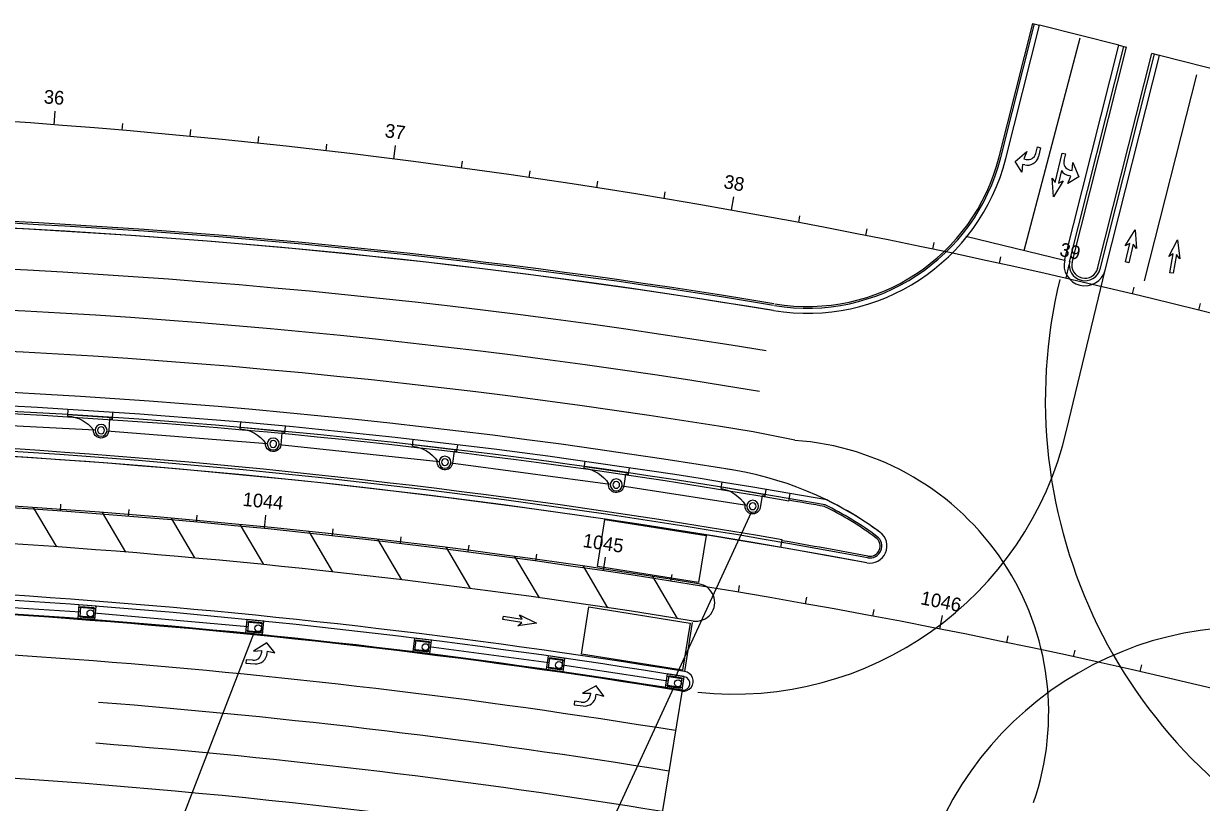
# Model space of a CAD drawing. Extents: x 468143 to 491361, y 1438528 to 1468730.
# Drawn here: x 486680.1 to 487025, y 1467383.7 to 1467611.7 of the extents above; entities that cross this region are included whole.
import ezdxf

# ---------------------------------------------------------------- set-up
doc = ezdxf.new("R2010")
doc.units = 0
doc.layers.add('Default', color=7, linetype='Continuous')
doc.layers.add('Xreference_dp', color=7, linetype='Continuous')

# ---------------------------------------------------------------- blocks, each defined once
blk = doc.blocks.new('POINT_DISPLAY')
at = {"layer": 'Default'}
blk.add_line((0, 0), (0, 0), dxfattribs=at)
blk = doc.blocks.new('InltCurb7_40')
at = {"layer": 'Default'}
for p, q in [((2.5, 4), (-2.5, 4)), ((-2.5, 4), (-2.5, 0)), ((2.5, 0), (2.5, 4)), ((2.5, 3.25), (-2.5, 3.25)), ((-2.5, 0.75), (2.5, 0.75)), ((-2.5, 0), (2.5, 0))]:
    blk.add_line(p, q, dxfattribs=at)
blk.add_lwpolyline([(-2, 0.5), (2, 0.5), (2, 3.5), (-2, 3.5)], close=True, dxfattribs=at)
blk.add_circle((-1.04, 2.19), 1, dxfattribs=at)
for p in [(-2, 3.5), (0, 4), (0, 3.5), (0, 3.5), (2, 3.5), (-2, 2), (-2, 2), (-2, 0.5), (0, 2), (0, 2), (0, 0.5), (0, 0.5), (0, 0), (0, 0), (2, 2), (2, 2), (2, 0.5)]:
    blk.add_blockref('POINT_DISPLAY', p, dxfattribs=at)
blk = doc.blocks.new('InltCurb1_35')
at = {"layer": 'Default'}
for p, q in [((2.25, 2), (2.25, 5.5)), ((-10, 2), (-10, 0)), ((-10, 1.5), (3, 1.5)), ((3, 2), (2.25, 2)), ((3, 0), (3, 2))]:
    blk.add_line(p, q, dxfattribs=at)
for radius in [1.75, 1]:
    blk.add_circle((0, 5.5), radius, dxfattribs=at)
for centre, radius, start, end in [((0, 5.5), 2.25, 0, 180), ((-9.85, 12), 10, 269.1432, 319.4677)]:
    blk.add_arc(centre, radius, start, end, dxfattribs=at)
for p in [(-0.66, 7.12), (0, 7.75), (0, 7.25), (0, 7.25), (0.7, 7.1), (-1.75, 5.5), (-1.75, 5.5), (-1.62, 4.84), (-1.6, 6.2), (-1.26, 4.28), (-1.22, 6.76), (-0.7, 3.9), (0, 5.5), (0, 5.5), (0, 3.75), (0, 3.75), (0.66, 3.88), (1.22, 4.24), (1.26, 6.72), (1.6, 4.8), (1.62, 6.16), (1.75, 5.5), (1.75, 5.5), (0, 0), (0, 0)]:
    blk.add_blockref('POINT_DISPLAY', p, dxfattribs=at)
blk = doc.blocks.new('DALeftTurn_1')
at = {"layer": 'Default'}
for points in [[(5.67, 3.17), (2, 0.5), (4.33, 0.83), (4.33, 0.17)], [(6, 0.17), (6, 0.83), (8.25, 0.5), (5.67, 3.17)], [(2, -2.17), (0, -2.17), (0, -3.17), (2.67, -3.17)]]:
    blk.add_lwpolyline(points, dxfattribs=at)
for centre, radius in [((2, 0.17), 2.33), ((2.67, 0.17), 3.33)]:
    blk.add_arc(centre, radius, 270, 0, dxfattribs=at)
blk = doc.blocks.new('DAThru_1')
at = {"layer": 'Default'}
blk.add_lwpolyline([(4.58, -1.67), (5.58, -0.5), (0, -0.5), (0, 0.5), (5.58, 0.5), (4.58, 1.67), (9.83, 0), (4.58, -1.67)], dxfattribs=at)
blk = doc.blocks.new('DALeftThru')
at = {"layer": 'Default'}
for points in [[(4.33, 0.83), (2, 0.5), (5.67, 3.17), (8.25, 0.5), (6, 0.83), (6, 0.17)], [(4.33, 0.17), (4.33, 0.83)], [(5.05, -2.17), (8.83, -2.17), (7.83, -1), (13.08, -2.67), (7.83, -4.33), (8.83, -3.17), (0, -3.17), (0, -2.17), (2, -2.17)]]:
    blk.add_lwpolyline(points, dxfattribs=at)
for centre, radius, start, end in [((2, 0.17), 2.33, 270, 0), ((2.67, 0.17), 3.33, 315.573, 360)]:
    blk.add_arc(centre, radius, start, end, dxfattribs=at)
blk = doc.blocks.new('DARightTurn')
at = {"layer": 'Default'}
for points in [[(2, 2.17), (0, 2.17), (0, 3.17), (2.67, 3.17)], [(5.67, -3.17), (2, -0.5), (4.33, -0.83), (4.33, -0.17)], [(6, -0.17), (6, -0.83), (8.25, -0.5), (5.67, -3.17)]]:
    blk.add_lwpolyline(points, dxfattribs=at)
for centre, radius in [((2, -0.17), 2.33), ((2.67, -0.17), 3.33)]:
    blk.add_arc(centre, radius, 360, 90, dxfattribs=at)
blk = doc.blocks.new('DAMerge_2')
at = {"layer": 'Default'}
blk.add_lwpolyline([(0.71, -4.09), (0, -3.39), (3.95, 0.56), (2.42, 0.68), (7.31, 3.21), (4.77, -1.68), (4.66, -0.15), (0.71, -4.09)], dxfattribs=at)
blk = doc.blocks.new('DAMerge_6')
at = {"layer": 'Default'}
blk.add_lwpolyline([(0.71, -4.09), (0, -3.39), (3.95, 0.56), (2.42, 0.68), (7.31, 3.21), (4.77, -1.68), (4.66, -0.15), (0.71, -4.09)], dxfattribs=at)

msp = doc.modelspace()

# ---------------------------------------------------------------- linework, layer by layer
at = {"layer": 'Xreference_dp'}
for p, q in [((486965.81, 1467572.63), (486975.67, 1467611.67)), ((486966.29, 1467572.5), (486976.16, 1467611.55)), ((486967.74, 1467572.14), (486977.61, 1467611.18)), ((486967.74, 1467572.14), (486977.61, 1467611.18)), ((486975.67, 1467611.67), (486977.61, 1467611.18)), ((487000.88, 1467605.3), (486977.61, 1467611.18)), ((486973.09, 1467545.2), (486989.53, 1467607.45)), ((486984.97, 1467542.32), (487000.88, 1467605.3)), ((486984.97, 1467542.32), (487000.88, 1467605.3)), ((486986.42, 1467541.95), (487002.33, 1467604.93)), ((486987.15, 1467541.77), (487003.06, 1467604.75)), ((487000.88, 1467605.3), (487003.06, 1467604.75)), ((486994.64, 1467540), (487010.53, 1467602.86)), ((486995.37, 1467539.82), (487011.25, 1467602.68)), ((486996.82, 1467539.45), (487012.71, 1467602.31)), ((486996.82, 1467539.45), (487012.71, 1467602.31)), ((487012.71, 1467602.31), (487010.53, 1467602.86)), ((487035.98, 1467596.43), (487012.71, 1467602.31)), ((487008.41, 1467536.34), (487023.66, 1467596.69)), ((486689.08, 1467582.05), (486689.38, 1467586.04)), ((486709.02, 1467580.44), (486709.19, 1467582.43)), ((486728.93, 1467578.63), (486729.13, 1467580.62)), ((486748.83, 1467576.62), (486749.04, 1467578.61)), ((486768.71, 1467574.41), (486768.94, 1467576.4)), ((486788.57, 1467572.01), (486789.07, 1467575.98)), ((486808.4, 1467569.4), (486808.67, 1467571.39)), ((486828.2, 1467566.6), (486828.49, 1467568.58)), ((486847.97, 1467563.6), (486848.28, 1467565.58)), ((486867.71, 1467560.4), (486868.04, 1467562.38)), ((486887.42, 1467557.01), (486888.12, 1467560.95)), ((486907.1, 1467553.42), (486907.47, 1467555.39)), ((486926.74, 1467549.63), (486927.13, 1467551.6)), ((486984.9, 1467542.34), (486956.09, 1467549.31)), ((486946.34, 1467545.65), (486946.74, 1467547.61)), ((486965.9, 1467541.47), (486966.32, 1467543.43)), ((486985.41, 1467537.1), (486986.31, 1467541)), ((486985.52, 1467492.5), (486996.82, 1467539.45)), ((487004.88, 1467532.53), (487005.35, 1467534.48)), ((487024.31, 1467527.77), (487024.79, 1467529.71)), ((486654.08, 1467495.19), (486701.06, 1467492.71)), ((486704.55, 1467492.47), (486751.48, 1467488.76)), ((486905.94, 1467489.67), (486893.74, 1467492.15)), ((486754.96, 1467488.43), (486801.79, 1467483.48)), ((486805.26, 1467483.07), (486851.94, 1467476.88)), ((486855.41, 1467476.38), (486891.91, 1467470.67)), ((486904.19, 1467471.87), (486904.58, 1467474.09)), ((486689.84, 1467458.5), (486683.04, 1467469.99)), ((486690.92, 1467468.95), (486691.06, 1467470.94)), ((486710.08, 1467456.95), (486703.23, 1467468.53)), ((486710.86, 1467467.43), (486711.03, 1467469.42)), ((486730.31, 1467455.22), (486723.41, 1467466.87)), ((486730.79, 1467465.72), (486730.97, 1467467.71)), ((486750.7, 1467463.82), (486751.1, 1467467.8)), ((486871.02, 1467420.38), (486893.33, 1467468.65)), ((486750.52, 1467453.28), (486743.57, 1467465.02)), ((486770.71, 1467451.15), (486763.71, 1467462.97)), ((486770.59, 1467461.73), (486770.81, 1467463.71)), ((486790.88, 1467448.82), (486783.84, 1467460.73)), ((486790.46, 1467459.45), (486790.7, 1467461.43)), ((486901.85, 1467458.32), (486902.23, 1467460.54)), ((486811.04, 1467446.3), (486803.93, 1467458.3)), ((486810.31, 1467456.98), (486810.56, 1467458.96)), ((486830.13, 1467454.32), (486830.41, 1467456.31)), ((486831.16, 1467443.58), (486824.01, 1467455.67)), ((486851.26, 1467440.66), (486844.05, 1467452.85)), ((486849.93, 1467451.48), (486850.51, 1467455.44)), ((486871.65, 1467437.5), (486864.38, 1467449.79)), ((486869.7, 1467448.45), (486870.01, 1467450.42)), ((486889.43, 1467445.22), (486889.77, 1467447.2)), ((486651.48, 1467442.35), (486696.7, 1467439.45)), ((486909.14, 1467441.81), (486909.49, 1467443.78)), ((486700.68, 1467439.14), (486745.82, 1467435.16)), ((486928.82, 1467438.22), (486929.18, 1467440.18)), ((486875.94, 1467436.3), (486873.7, 1467421.98)), ((486948.45, 1467434.43), (486949.23, 1467438.36)), ((486747.66, 1467433.47), (486722.51, 1467368.52)), ((486968.06, 1467430.46), (486968.46, 1467432.42)), ((486833.93, 1467424.5), (486798.8, 1467429.21)), ((486987.62, 1467426.3), (486988.04, 1467428.26)), ((486837.89, 1467423.94), (486868.8, 1467419.22)), ((487007.14, 1467421.96), (487007.58, 1467423.91)), ((486870.54, 1467417.42), (486841.12, 1467353.6)), ((486872.94, 1467416.53), (486865.25, 1467369.15))]:
    msp.add_line(p, q, dxfattribs=at)
for points in [[(486848.15, 1467452.7), (486850.33, 1467466.53), (486879.96, 1467461.84), (486877.78, 1467448.01)], [(486843.47, 1467427.05), (486845.66, 1467440.88), (486875.29, 1467436.19), (486873.1, 1467422.36)]]:
    msp.add_lwpolyline(points, close=True, dxfattribs=at)
for centre, radius, start, end in [((486537.7, 1465584.94), 2002.84, 65.37329, 99.90546), ((486909.57, 1467586.84), 60, 260.5938, 345.8192), ((486909.57, 1467586.84), 60, 260.5938, 345.8192), ((486909.57, 1467586.84), 58.5, 260.5938, 345.8192), ((486909.57, 1467586.84), 58, 260.5938, 345.8192), ((486576.17, 1465574.26), 1982, 80.60151, 94.91832), ((486576.17, 1465574.26), 1980, 80.60151, 99.90595), ((486576.17, 1465574.26), 1980, 80.59384, 95.2178), ((486576.17, 1465574.26), 1981.5, 80.60151, 94.91867), ((486576.17, 1465574.26), 1968, 80.60151, 99.90595), ((486990.92, 1467540.98), 6.1, 165.8192, 345.8192), ((486990.92, 1467540.98), 6.1, 165.8192, 345.8192), ((486990.92, 1467540.98), 4.6, 165.8192, 345.8192), ((486990.92, 1467540.98), 4.6, 165.8192, 345.8192), ((486990.92, 1467540.98), 3.85, 165.8192, 345.8192), ((487129.34, 1467501.5), 150, 166.3971, 245.8239), ((486576.17, 1465574.26), 1956, 80.60151, 99.90595), ((486576.17, 1465574.26), 1944, 80.59814, 99.90595), ((486576.17, 1465574.26), 1932, 80.72286, 99.90595), ((486576.17, 1465574.26), 1928, 79.86924, 94.15426), ((486576.17, 1465574.26), 1926.5, 79.87546, 94.1553), ((486576.17, 1465574.26), 1925.75, 80.19274, 94.15581), ((486541.29, 1465374.28), 2117.25, 80.18456, 92.82593), ((486541.29, 1465374.28), 2116.5, 79.49165, 92.82593), ((486888.17, 1467515.37), 100, 263.9288, 346.7835), ((486541.29, 1465374.28), 2115, 79.49165, 99.02499), ((486541.29, 1465374.28), 2115, 79.49165, 92.82593), ((486900.31, 1467409.86), 80, 340.8949, 85.9634), ((486871.51, 1467382.3), 100, 53.5595, 81.8523), ((486541.29, 1465374.28), 2100, 65.36712, 99.90595), ((486541.29, 1465374.28), 2100.5, 80.78193, 95.46596), ((486576.17, 1465574.26), 1926, 79.87546, 80.19274), ((486871.51, 1467382.3), 98, 53.5595, 63.9094), ((486871.51, 1467382.3), 98.5, 53.5595, 63.9094), ((486871.51, 1467382.3), 100, 53.5595, 64.0304), ((486541.29, 1465374.28), 2089.5, 80.77624, 91.44817), ((486927.94, 1467458.73), 5, 259.4917, 53.5595), ((486927.94, 1467458.73), 5, 259.4917, 53.5595), ((486541.29, 1465374.28), 2117, 79.49165, 80.18456), ((486927.94, 1467458.73), 3.5, 259.4917, 53.5595), ((486927.94, 1467458.73), 3.5, 259.4917, 53.5595), ((486927.94, 1467458.73), 3, 259.4917, 53.5595), ((486541.29, 1465374.28), 2074.5, 80.77953, 91.44817), ((486541.29, 1465374.28), 2073, 80.77655, 91.44817), ((486877.01, 1467442.21), 5.5, 261.8059, 81.9178), ((486541.29, 1465374.28), 2069, 80.77607, 91.44817), ((486541.29, 1465374.28), 2068.75, 80.77607, 91.44817), ((487039.15, 1467335.06), 100, 75.7532, 164.5462), ((486541.29, 1465374.28), 2057, 80.77607, 90.64932), ((486873.31, 1467419.13), 2.88, 261.7666, 82.2828), ((486873.25, 1467418.5), 2, 261.026, 81.026), ((486541.29, 1465374.28), 2045, 80.77607, 85.49138), ((486541.29, 1465374.28), 2033, 80.77607, 85.4857), ((486541.29, 1465374.28), 2021, 78.93045, 91.44817)]:
    msp.add_arc(centre, radius, start, end, dxfattribs=at)

# ---------------------------------------------------------------- block references
for name, p, rotation in [('DARightTurn', (486974.88, 1467576.07), -103.81699360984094), ('DALeftThru', (486987.36, 1467573.03), -103.2639526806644), ('DAMerge_2', (487001.04, 1467544.77), 31.600146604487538), ('DAMerge_6', (487001.04, 1467544.77), 31.600146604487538), ('DAMerge_2', (487013.83, 1467541.54), 34.359727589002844), ('DAMerge_6', (487013.83, 1467541.54), 34.359727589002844), ('InltCurb7_40', (486698.84, 1467441.29), 175.6067494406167), ('DAThru_1', (486820.57, 1467437.69), -8.98934022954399), ('InltCurb7_40', (486748.01, 1467436.95), 174.3116721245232), ('InltCurb7_40', (486797.06, 1467431.44), 172.94750036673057), ('DALeftTurn_1', (486745.46, 1467427.58), -4.08633624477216), ('InltCurb7_40', (486836.19, 1467426.2), 171.8561342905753), ('DALeftTurn_1', (486841.77, 1467415.42), -8.010833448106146), ('InltCurb7_40', (486871.1, 1467420.88), 170.84522550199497)]:
    msp.add_blockref(name, p, dxfattribs=dict(at, rotation=rotation))
for p, yscale, rotation in [((486703.17, 1467498.08), -1.0000000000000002, -3.821479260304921), ((486753.73, 1467494.07), -1.0000000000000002, -5.3287835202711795), ((486804.18, 1467488.73), -1.0000000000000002, -6.836337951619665), ((486854.47, 1467482.07), -1.0000000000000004, -8.34405793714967), ((486894.57, 1467475.79), -1.0000000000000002, -9.839044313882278)]:
    msp.add_blockref('InltCurb1_35', p, dxfattribs=dict(at, yscale=yscale, rotation=rotation))

# ---------------------------------------------------------------- texts
for s, rotation, p in [('36', 355.6653, (486685.95, 1467588.31)), ('37', 352.8046, (486785.75, 1467578.41)), ('38', 349.9439, (486884.94, 1467563.55)), ('39', 347.0831, (486983.25, 1467543.75)), ('1044', 354.2771, (486744.15, 1467470.5)), ('1045', 351.5487, (486843.7, 1467458.47)), ('1046', 348.8204, (486942.57, 1467441.71))]:
    msp.add_text(s, height=4, rotation=rotation, dxfattribs=at).set_placement(p)

doc.saveas('drawing.dxf')
